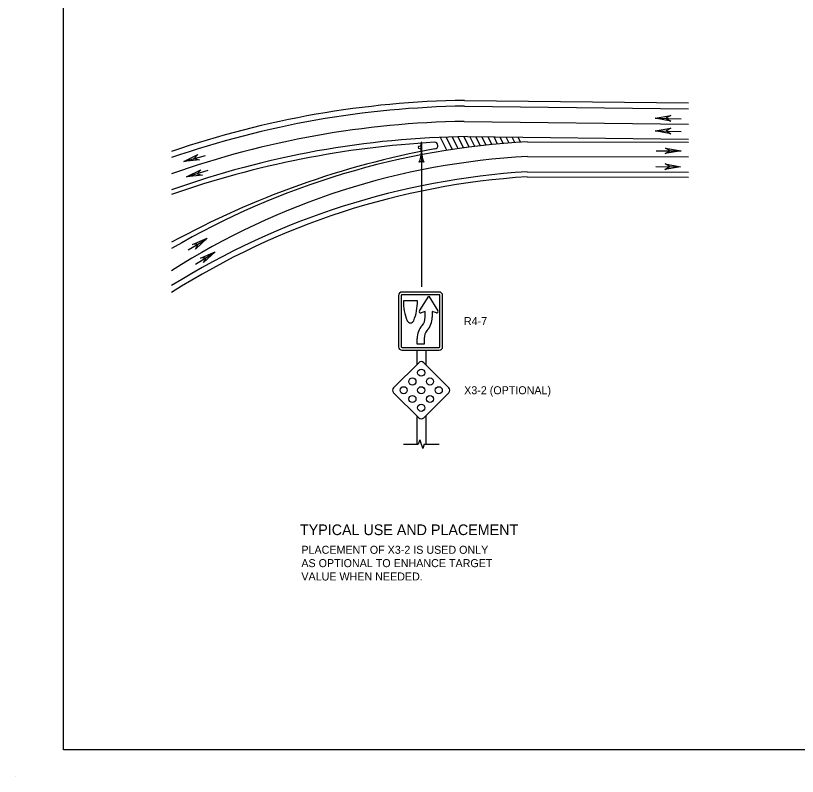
# Model space of a CAD drawing. Extents: x 49991.4 to 50021, y 49987.6 to 50011.4.
# Drawn here: x 49999.02 to 50004.88, y 49987.6 to 49993.3 of the extents above; entities that cross this region are included whole.
import ezdxf

# ---------------------------------------------------------------- set-up
doc = ezdxf.new("R2010")
doc.units = 0
for name, color, linetype in [('Level 1', 7, 'Continuous'), ('Level 2', 7, 'Continuous'), ('Level 3', 7, 'Continuous'), ('Level 4', 7, 'Continuous'), ('Level 5', 7, 'Continuous'), ('Level 6', 7, 'Continuous')]:
    doc.layers.add(name, color=color, linetype=linetype)

msp = doc.modelspace()

# ---------------------------------------------------------------- linework, layer by layer
at = {"layer": 'Level 1'}
for p, q in [((50002.3866, 49992.6208), (50004.0647, 49992.601)), ((50003.8143, 49992.5311), (50004.009, 49992.5259)), ((50003.8159, 49992.4357), (50004.0106, 49992.4305)), ((50002.0667, 49992.3475), (50002.0633, 49992.3475)), ((50002.0633, 49992.2773), (50002.0633, 49992.3475)), ((50002.0667, 49992.2773), (50002.0667, 49992.3475)), ((50002.2555, 49992.2897), (50002.2068, 49992.3869)), ((50002.2971, 49992.2961), (50002.2507, 49992.3886)), ((50002.3387, 49992.3022), (50002.2947, 49992.39)), ((50002.3806, 49992.3081), (50002.339, 49992.3911)), ((50002.4225, 49992.3136), (50002.3832, 49992.392)), ((50002.4084, 49992.3923), (50004.0647, 49992.3722)), ((50002.4646, 49992.3189), (50002.4279, 49992.3921)), ((50002.5069, 49992.3238), (50002.473, 49992.3915)), ((50002.5492, 49992.3285), (50002.5179, 49992.391)), ((50002.5918, 49992.3329), (50002.563, 49992.3904)), ((50002.6345, 49992.337), (50002.608, 49992.3899)), ((50002.6773, 49992.3408), (50002.6529, 49992.3893)), ((50002.7204, 49992.3442), (50002.6981, 49992.3888)), ((50002.7633, 49992.3474), (50002.7429, 49992.3882)), ((50002.8067, 49992.3503), (50002.788, 49992.3877)), ((50002.8583, 49992.3533), (50004.0648, 49992.3507)), ((50003.8221, 49992.287), (50004.0088, 49992.2851)), ((50000.2842, 49992.2053), (50000.4478, 49992.251)), ((50002.0633, 49992.2773), (50002.0667, 49992.2773)), ((50003.8191, 49992.1687), (50004.0058, 49992.1667)), ((50000.305, 49992.0901), (50000.4669, 49992.1413)), ((50002.856, 49992.129), (50004.0643, 49992.1264)), ((50000.3163, 49991.5438), (50000.4481, 49991.6222)), ((50000.3711, 49991.4374), (50000.5095, 49991.5213)), ((50002.1969, 49991.2278), (50001.9191, 49991.2278)), ((50001.893, 49991.2017), (50001.893, 49990.8181)), ((50001.913, 49991.2017), (50001.913, 49990.8181)), ((50002.1969, 49991.2078), (50001.9191, 49991.2078)), ((50002.0492, 49991.0866), (50002.1187, 49991.1967)), ((50002.1187, 49991.1967), (50002.1881, 49991.0866)), ((50002.203, 49990.8181), (50002.203, 49991.2017)), ((50002.223, 49990.8181), (50002.223, 49991.2017)), ((50002.0348, 49991.1621), (50001.929, 49991.1621)), ((50002.0349, 49991.162), (50002.0348, 49991.1621)), ((50002.0491, 49991.0866), (50002.0492, 49991.0866)), ((50002.0923, 49991.0809), (50002.0612, 49991.071)), ((50002.0923, 49991.0386), (50002.0923, 49991.0809)), ((50002.1761, 49991.071), (50002.1451, 49991.0809)), ((50002.1451, 49991.0809), (50002.1451, 49991.0386)), ((50002.0315, 49990.8379), (50002.0315, 49990.8798)), ((50002.0845, 49990.8798), (50002.0845, 49990.8379)), ((50002.0845, 49990.8379), (50002.0315, 49990.8379)), ((50001.9191, 49990.812), (50002.1969, 49990.812)), ((50001.9191, 49990.792), (50002.1969, 49990.792)), ((50002.0294, 49990.792), (50002.0294, 49990.6842)), ((50002.0969, 49990.792), (50002.0969, 49990.6828)), ((50001.8557, 49990.5106), (50002.0437, 49990.6985)), ((50002.0812, 49990.6985), (50002.2691, 49990.5106)), ((50002.0437, 49990.2852), (50001.8557, 49990.4731)), ((50002.2691, 49990.4731), (50002.0812, 49990.2852)), ((50002.1281, 49990.4261), (50002.1281, 49990.4261)), ((50002.1281, 49990.4261), (50002.1281, 49990.4261)), ((50002.1281, 49990.4261), (50002.1281, 49990.4261)), ((50002.1281, 49990.4261), (50002.1281, 49990.4261)), ((50002.0294, 49990.2995), (50002.0294, 49990.0874)), ((50002.0969, 49990.3009), (50002.0969, 49990.0874)), ((49999.0245, 49987.5988), (49999.0245, 49987.5988))]:
    msp.add_line(p, q, dxfattribs=at)
for points in [[(49999.3835, 49998.9992), (50016.7501, 49998.9992), (50016.7501, 49987.7988), (49999.3835, 49987.7988)], [(50003.9315, 49992.509), (50003.8143, 49992.5311), (50003.9319, 49992.5504), (50003.896, 49992.5304)], [(50003.9331, 49992.4136), (50003.8159, 49992.4357), (50003.9335, 49992.455), (50003.8976, 49992.435)], [(50003.8916, 49992.3071), (50004.0088, 49992.2851), (50003.8912, 49992.2659), (50003.9271, 49992.2861)], [(50000.4024, 49992.2188), (50000.2842, 49992.2053), (50000.3904, 49992.2586), (50000.3621, 49992.2282)], [(50003.8889, 49992.1886), (50004.0058, 49992.1667), (50003.8884, 49992.1471), (50003.9244, 49992.1677)], [(50000.4233, 49992.1041), (50000.305, 49992.0901), (50000.4115, 49992.1438), (50000.3833, 49992.1136)], [(50000.3501, 49991.5848), (50000.4593, 49991.6324), (50000.373, 49991.5503), (50000.3913, 49991.5873)], [(50000.4096, 49991.4825), (50000.5188, 49991.5301), (50000.4325, 49991.448), (50000.4508, 49991.485)]]:
    msp.add_lwpolyline(points, close=True, dxfattribs=at)
for centre, radius in [((50002.0523, 49992.3124), 0.011), ((50002.0624, 49990.6234), 0.0266), ((50001.9967, 49990.5576), 0.0266), ((50002.1281, 49990.5576), 0.0266), ((50001.9309, 49990.4919), 0.0266), ((50002.0624, 49990.4919), 0.0266), ((50002.1939, 49990.4919), 0.0266), ((50001.9967, 49990.4262), 0.0266), ((50002.1281, 49990.4262), 0.0266), ((50002.0624, 49990.3604), 0.0266)]:
    msp.add_circle(centre, radius, dxfattribs=at)
for centre, radius, start, end in [((50002.4919, 49985.5872), 7.0344, 90.85766, 109.07849), ((50002.4919, 49985.5872), 6.8057, 90.70289, 109.74568), ((50003.1766, 49986.4492), 5.9127, 93.0858, 120.3094), ((50003.2114, 49986.4362), 5.7039, 93.57167, 121.95451), ((50001.9191, 49991.2017), 0.0261, 90, 180), ((50002.1969, 49991.2017), 0.0261, 0, 90), ((50001.9191, 49991.2017), 0.00606, 90, 180), ((50002.1969, 49991.2017), 0.00606, 0, 90), ((50002.3259, 49991.1606), 0.3969, 179.79525, 201.78786), ((50001.638, 49991.1606), 0.3969, 338.21242, 0.20499), ((50002.058, 49991.081), 0.0105, 147.75701, 287.61864), ((50002.1793, 49991.081), 0.0105, 252.38039, 32.24384), ((50001.9819, 49991.0231), 0.0265, 201.78767, 338.21322), ((50001.9996, 49991.0385), 0.0926, 318.19008, 0), ((50001.9996, 49991.0385), 0.1455, 318.19008, 0), ((50002.1771, 49990.8798), 0.1455, 138.19027, 180), ((50002.1771, 49990.8798), 0.0926, 138.19027, 180), ((50001.9191, 49990.8181), 0.0261, 180, 270), ((50001.9191, 49990.8181), 0.00606, 180, 270), ((50002.1969, 49990.8181), 0.00606, 270, 0), ((50002.1969, 49990.8181), 0.0261, 270, 0.07969), ((50002.0624, 49990.6797), 0.0266, 45, 135), ((50001.8745, 49990.4918), 0.0266, 135, 225), ((50002.2503, 49990.4918), 0.0266, 315, 45), ((50002.0624, 49990.304), 0.0266, 225, 315)]:
    msp.add_arc(centre, radius, start, end, dxfattribs=at)
at = {"layer": 'Level 3'}
msp.add_line((50002.065, 49992.2773), (50002.065, 49991.2678), dxfattribs=at)
for centre, radius, start, end in [((50001.8429, 49992.2865), 0.2223, 337.45601, 357.63952), ((50002.2977, 49992.2888), 0.233, 182.82731, 202.07716), ((50002.065, 49992.1491), 0.0548, 72.13882, 107.86118)]:
    msp.add_arc(centre, radius, start, end, dxfattribs=at)
at = {"layer": 'Level 4'}
for p, q in [((50002.3871, 49992.6642), (50004.0647, 49992.6444)), ((50002.1648, 49992.3015), (50002.1648, 49992.3013)), ((50002.8566, 49992.0914), (50004.0642, 49992.0888))]:
    msp.add_line(p, q, dxfattribs=at)
for centre, radius, start, end in [((50002.4919, 49985.5872), 7.0778, 90.84835, 108.95702), ((50002.5611, 49985.1849), 7.1761, 93.1826, 109.27139), ((50002.1637, 49992.3257), 0.0242, 272.47265, 92.44136), ((50003.3597, 49985.8121), 6.5983, 100.43398, 118.68499), ((50003.213, 49986.4711), 5.6316, 93.62866, 122.43459)]:
    msp.add_arc(centre, radius, start, end, dxfattribs=at)
at = {"layer": 'Level 5'}
for p, q in [((50002.3852, 49992.5064), (50004.0647, 49992.4866)), ((50002.858, 49992.2434), (50004.0645, 49992.2408))]:
    msp.add_line(p, q, dxfattribs=at)
for centre, radius, start, end in [((50002.4919, 49985.5872), 6.9201, 90.88343, 109.40631), ((50003.1459, 49986.77), 5.481, 93.01134, 122.60388)]:
    msp.add_arc(centre, radius, start, end, dxfattribs=at)
at = {"layer": 'Level 6'}
for p, q in [((50002.0517, 49990.1194), (50002.0403, 49990.0874)), ((50002.0517, 49990.1194), (50002.0631, 49990.0874)), ((50001.9294, 49990.0874), (50002.0403, 49990.0874)), ((50002.0631, 49990.0874), (50002.0744, 49990.0554)), ((50002.0857, 49990.0874), (50002.0744, 49990.0554)), ((50002.0857, 49990.0874), (50002.1969, 49990.0874))]:
    msp.add_line(p, q, dxfattribs=at)

# ---------------------------------------------------------------- texts
at = {"layer": 'Level 2'}
for s, height, p in [('R4-7', 0.06, (50002.3827, 49990.9799)), ('X3-2 (OPTIONAL)', 0.06, (50002.3843, 49990.4619)), ('TYPICAL USE AND PLACEMENT', 0.08, (50001.1545, 49989.4066)), ('PLACEMENT OF X3-2 IS USED ONLY', 0.06, (50001.1649, 49989.2666)), ('AS OPTIONAL TO ENHANCE TARGET ', 0.06, (50001.1649, 49989.1666)), ('VALUE WHEN NEEDED.  ', 0.06, (50001.1649, 49989.0666))]:
    msp.add_text(s, height=height, dxfattribs=at).set_placement(p)

doc.saveas('drawing.dxf')
